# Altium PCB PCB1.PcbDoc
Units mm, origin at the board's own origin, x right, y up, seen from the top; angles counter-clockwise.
Board outline 108.7 x 104.5 mm, 2 copper layers (Top Layer, Bottom Layer); 73 components, 40 nets, 200 pads, 22 vias.
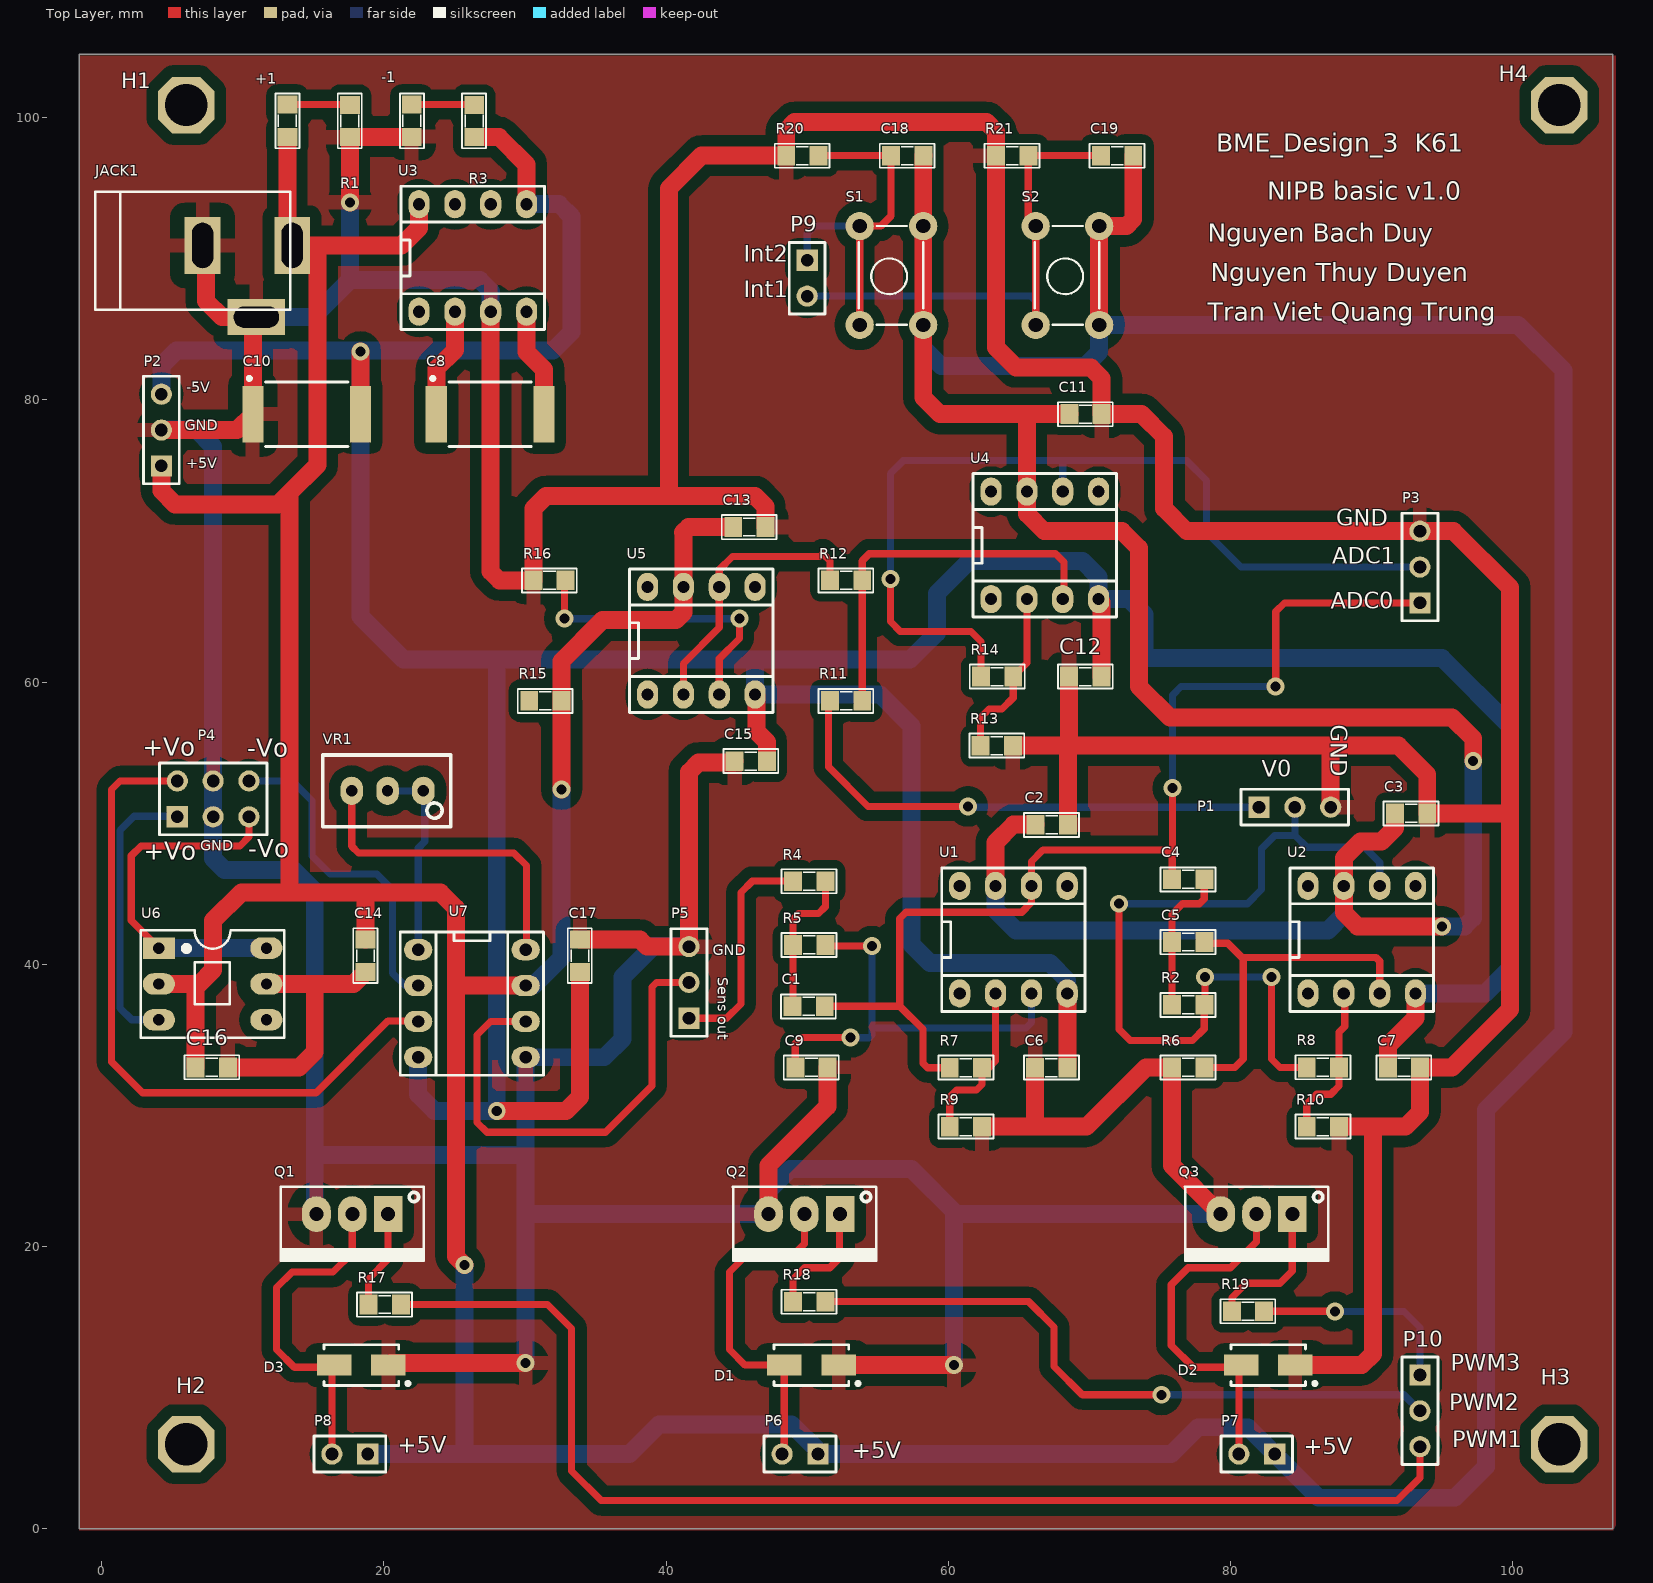
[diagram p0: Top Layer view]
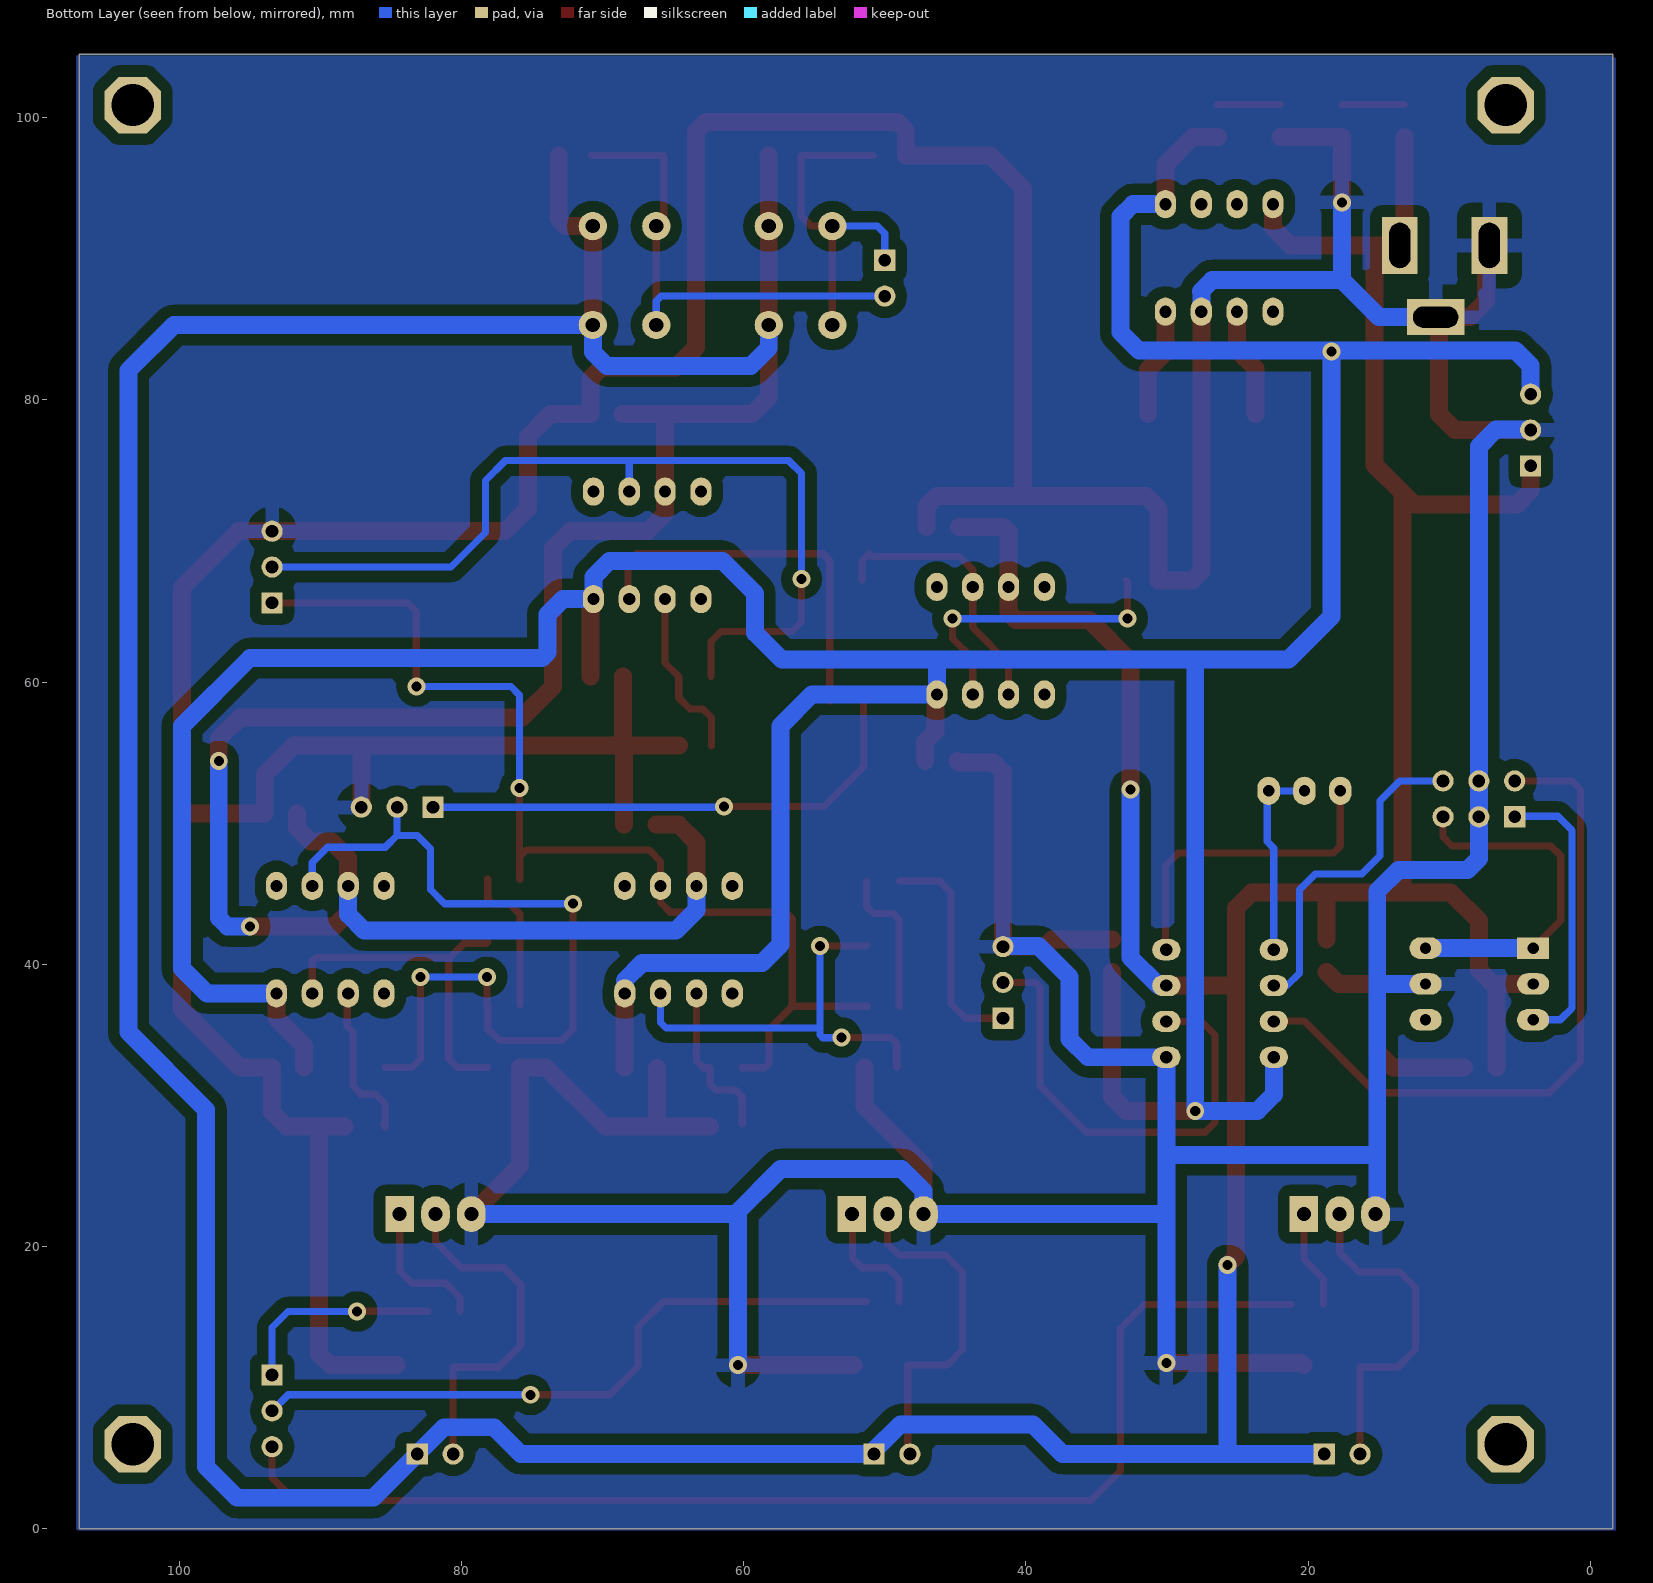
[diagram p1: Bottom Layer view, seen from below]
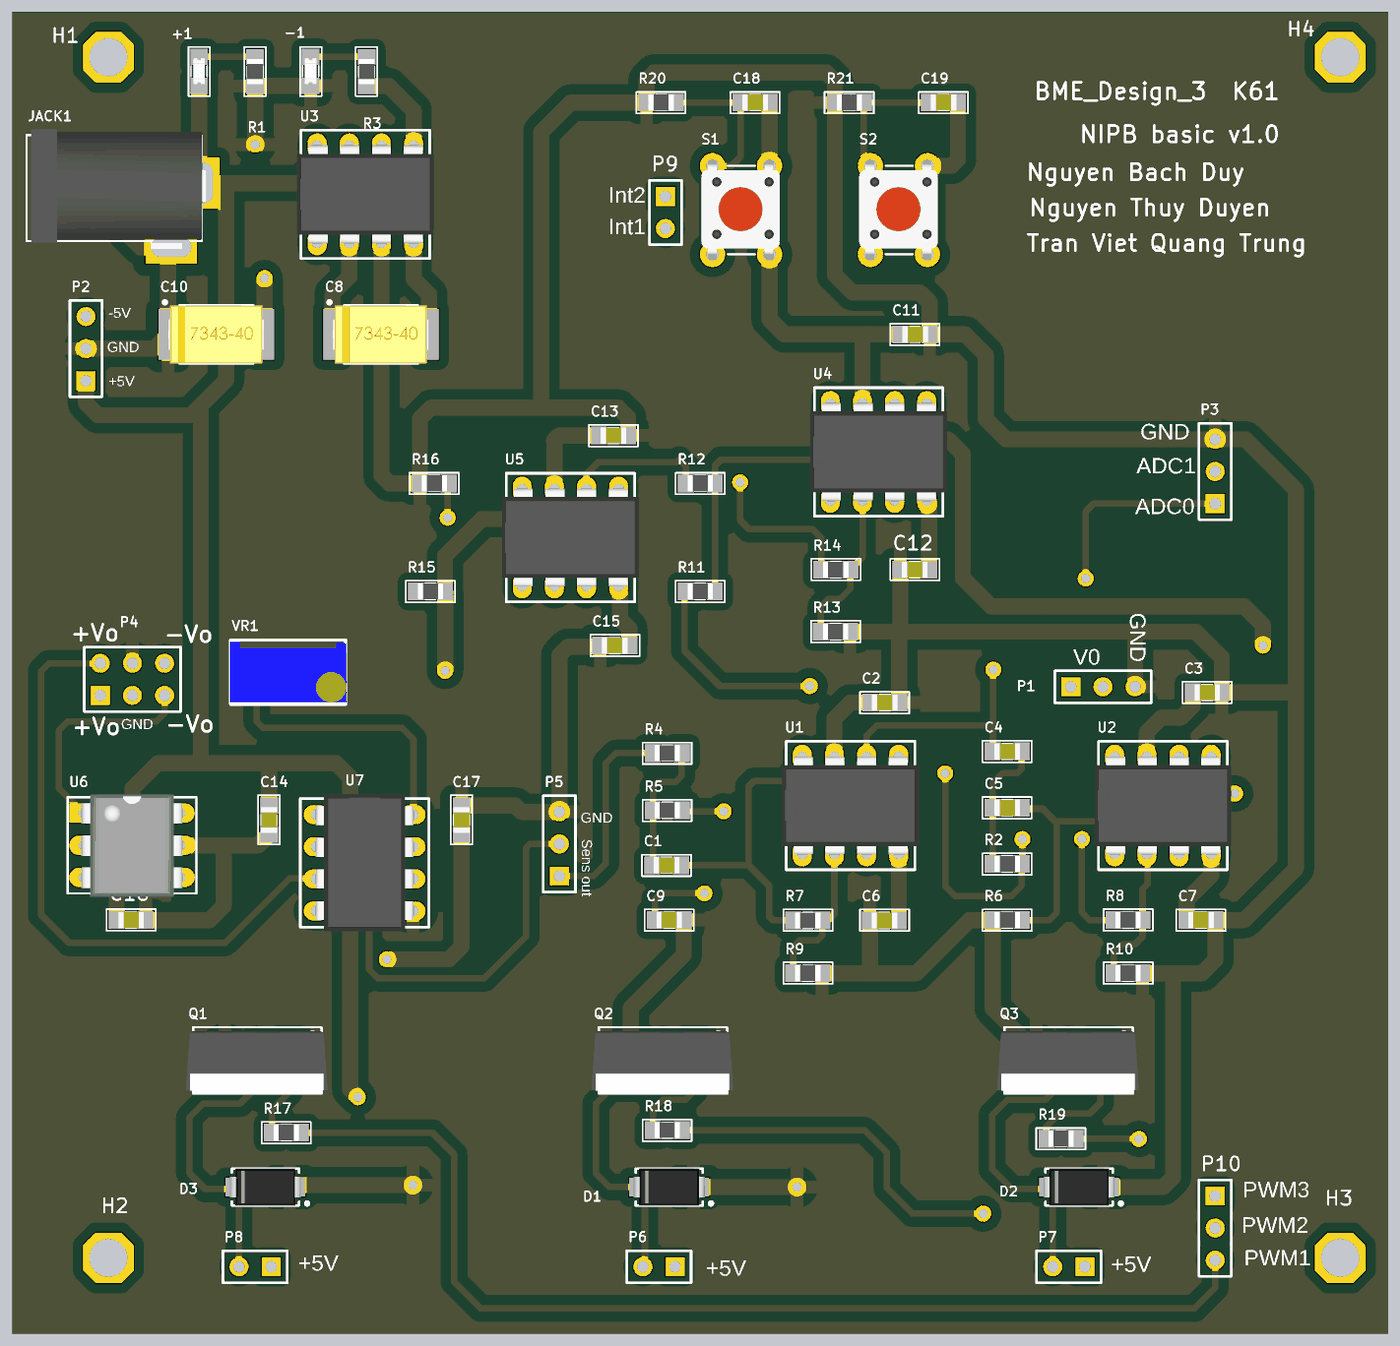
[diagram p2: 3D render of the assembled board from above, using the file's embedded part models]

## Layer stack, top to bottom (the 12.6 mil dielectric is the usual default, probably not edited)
Top Solder: solder mask 0.0102, Solder Resist, Dk 3.5
Top Layer: signal copper 0.0356
Dielectric 1: dielectric 0.32, FR-4, Dk 4.8
Bottom Layer: signal copper 0.0356
Bottom Solder: solder mask 0.0102, Solder Resist, Dk 3.5

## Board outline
-1.6,0 107.1,0 107.1,104.5 -1.6,104.5

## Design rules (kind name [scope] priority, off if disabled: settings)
Clearance Clearance_1 [All] p1: gap=0.4 ignorepadtopadclearanceinfootprint=FALSE except(0.8: Arc-Fill Arc-Poly Arc-Region Track-Fill Track-Poly Track-Region SMDPad-Fill SMDPad-Poly SMDPad-Region THPad-Fill THPad-Poly THPad-Region Via-Fill Via-Poly Via-Region Fill-Fill Fill-Poly Fill-Region Poly-Poly Poly-Region Region-Region)
Clearance polygon_clearance [InPolygon] p2: gap=2 ignorepadtopadclearanceinfootprint=FALSE
PolygonConnect [All] p1: connectstyle=Relief reliefconductorwidth=1 reliefentries=4 polygonreliefangle="90 Angle" airgapwidth=1
RoutingVias [All] p1: holewidth=1.016 width=0.635 viastyle="Through Hole" minholewidth=1.016 minwidth=0.635 maxholewidth=1.016 maxwidth=0.635
SolderMaskExpansion [All] p1: expansion=0.102
Width [All] p1: maxlimit=1.27 minlimit=0.3 preferedwidth=0.508
30 further rules are at their usual default settings.

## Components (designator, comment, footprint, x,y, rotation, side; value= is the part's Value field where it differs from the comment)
+1 "LED" "LED SMD 0805" 13.1,99.8 r90 top
-1 "LED" "LED SMD 0805" 21.906,99.8 r90 top
C1 "1uF" "0805 CAP" 50.1,37.039 r0 top
C2 "104" "0805 CAP" 67.325,49.9 r0 top
C3 "104" "0805 CAP" 92.8,50.7 r0 top
C4 "10uF" "0805 CAP" 77,46.035 r0 top
C5 "10uF" "0805 CAP" 77,41.59 r0 top
C6 "104" "0805 CAP" 67.3,32.675 r180 top
C7 "104" "0805 CAP" 92.3,32.7 r0 top
C8 "10uF" "CAP TANTALUM SMD7434" 27.4,78.989 r0 top
C9 "1uF" "0805 CAP" 50.3,32.7 r0 top
C10 "10uF" "CAP TANTALUM SMD7434" 14.4,78.989 r0 top
C11 "104" "0805 CAP" 69.725,79 r0 top
C12 "104" "0805 CAP" 69.7,60.4 r180 top
C13 "104" "0805 CAP" 45.904,71 r0 top
C14 "104" "0805 CAP" 18.7,40.61 r270 top
C15 "104" "0805 CAP" 46,54.4 r180 top
C16 "104" "0805 CAP" 7.8,32.7 r180 top
C17 "104" "0805 CAP" 33.9,40.61 r270 top
C18 "104" "0805 CAP" 57.093,97.315 r0 top
C19 "104" "0805 CAP" 71.964,97.315 r0 top
D1 "DIODE" "DIODE SMA" 50.3,11.6 r180 top
D2 "DIODE" "DIODE SMA" 82.674,11.6 r180 top
D3 "DIODE" "DIODE SMA" 18.4,11.6 r180 top
H1 "HOLE" HOLE 6,100.9 r0 top
H2 "HOLE" HOLE 6,6 r0 top
H3 "HOLE" HOLE 103.3,6 r0 top
H4 "HOLE" HOLE 103.3,100.9 r0 top
JACK1 "JACK DC" "JACK DC" 10.328,88.41 r0 top value="Jac DC"
P1 "Header 3H" HDR1X3 82.02,51.143 r0 top
P2 "Header 3H" HDR1X3 4.232,75.329 r90 top
P3 "Header 3H" HDR1X3 93.424,65.62 r90 top
P4 "Header 3X2" HDR2X3 5.36,50.46 r0 top
P5 "Header 3H" HDR1X3 41.623,36.179 r90 top
P6 "Valve" HDR1X2 50.76,5.3 r180 top
P7 "Valve" HDR1X2 83.134,5.3 r180 top
P8 "Pump" HDR1X2 18.86,5.3 r180 top
P9 "Header 2H" HDR1X2 50,89.9 r270 top
P10 "Header 3H" HDR1X3 93.424,10.9 r270 top
Q1 "TIP41C" QTO-220 20.3,22.3 r180 top
Q2 "TIP41C" QTO-220 52.34,22.3 r180 top
Q3 "TIP41C" QTO-220 84.38,22.3 r180 top
R1 "10k" "0805 RESISTOR" 17.594,100.908 r270 top value="R1/4W - 1K"
R2 "33k" "0805 RESISTOR" 75.857,37.145 r0 top value="R1/4W - 1K"
R3 "10k" "0805 RESISTOR" 26.4,100.908 r270 top value="R1/4W - 1K"
R4 "33k" "0805 RESISTOR" 49,45.9 r0 top value="R1/4W - 1K"
R5 "33k" "0805 RESISTOR" 49,41.378 r0 top value="R1/4W - 1K"
R6 "33K" "0805 RESISTOR" 75.857,32.7 r0 top value="R1/4W - 1K"
R7 "5.6k" "0805 RESISTOR" 62.386,32.675 r180 top value="R1/4W - 1K"
R8 "5.6k" "0805 RESISTOR" 87.686,32.7 r180 top value="R1/4W - 1K"
R9 "10k" "0805 RESISTOR" 62.386,28.5 r180 top value="R1/4W - 1K"
R10 "10k" "0805 RESISTOR" 87.686,28.5 r180 top value="R1/4W - 1K"
R11 "10k" "0805 RESISTOR" 51.614,58.684 r0 top value="R1/4W - 1K"
R12 "10k" "0805 RESISTOR" 51.614,67.218 r0 top value="R1/4W - 1K"
R13 "10k" "0805 RESISTOR" 64.575,55.5 r180 top value="R1/4W - 1K"
R14 "10k" "0805 RESISTOR" 64.6,60.4 r180 top value="R1/4W - 1K"
R15 "10k" "0805 RESISTOR" 30.3,58.684 r0 top value="R1/4W - 1K"
R16 "2.2k" "0805 RESISTOR" 30.6,67.218 r0 top value="R1/4W - 1K"
R17 "10k" "0805 RESISTOR" 18.914,15.9 r0 top value="R1/4W - 1K"
R18 "10k" "0805 RESISTOR" 49,16.1 r0 top value="R1/4W - 1K"
R19 "10k" "0805 RESISTOR" 80.1,15.425 r0 top value="R1/4W - 1K"
R20 "10k" "0805 RESISTOR" 48.515,97.315 r0 top value="R1/4W - 1K"
R21 "10k" "0805 RESISTOR" 63.386,97.315 r0 top value="R1/4W - 1K"
S1 "SWITCH" "SW 4PIN" 58.222,92.318 r270 top
S2 "SWITCH" "SW 4PIN" 70.694,92.318 r270 top
U1 "LM741" "DIP 8" 64.617,41.755 r0 top
U2 "LM741" "DIP 8" 89.3,41.755 r0 top
U3 "ICL7660" "DIP 8" 26.3,90.064 r0 top
U4 "LM741" "DIP 8" 66.838,69.7 r0 top
U5 "LM741" "DIP 8" 42.498,62.938 r0 top
U6 "MPS20N0040D" "DIP 6" 4.056,41.153 r270 top
U7 "INA-129" "DIP 8" 26.241,37.229 r270 top
VR1 "10K" RVAR 20.26,52.3 r180 top value="VR 10K"

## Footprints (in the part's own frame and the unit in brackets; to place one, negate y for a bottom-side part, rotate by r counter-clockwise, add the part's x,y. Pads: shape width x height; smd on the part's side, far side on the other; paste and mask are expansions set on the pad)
"0805 CAP" [mil] "Compoment SMD 80x50mil"
  rect 50x55 smd: 1(-45,0) 2(45,0)
  silkscreen extent -77,-34 76,33, body extent -40,-25 40,25, height 24
"0805 RESISTOR" [mil] "Compoment SMD 80x50mil"
  rect 50x55 smd: 1(0,0) 2(90,0)
  silkscreen extent -32,-34 121,33, body extent 6,-25 84,25, height 24
"CAP TANTALUM SMD7434" [mm] "227C-220uF 16V"
  rect 1.5x4 smd: 1(-3.683,0) 2(3.937,0)
  silkscreen extent -4.06,-2.29 3.05,2.66, body extent -3.68,-2.3 3.92,2.3, height 4
"DIODE SMA" [mm]
  rect 2.45x1.5 smd: 1(-1.925,0) 2(1.925,0)
  silkscreen extent -3.43,-1.45 2.65,1.45, body extent -2.8,-1.48 2.8,1.47, height 2.7
"DIP 6" [mil] "6 PIN, W 300mil, Pin to pin 100mil"
  rect 60x90 hole 31.5: 1(0,0)
  oval 60x90 hole 31.5: 2(100,0) 3(200,0) 4(200,300) 5(100,300) 6(0,300)
  silkscreen extent -50,-50 250,350, body extent -58,-7 260,307, height 170
"DIP 8" [mm] "W.300/L.400"
  oval 1.5x2 hole 0.864: 1(-3.81,-3.81) 2(-1.27,-3.81) 3(1.27,-3.81) 4(3.81,-3.81) 5(3.81,3.81) 6(1.27,3.81) 7(-1.27,3.81) 8(-3.81,3.81)
  silkscreen extent -5.08,-5.08 5.08,5.08, body extent -5.4,-3.88 5.4,3.88, height 4.5
HDR1X2 [mm] "Connector; Header; 2 Position"
  rect 1.5x1.5 hole 0.9: 1(0,0)
  round 1.5 hole 0.9: 2(2.54,0)
  silkscreen extent -1.27,-1.27 3.81,1.27
HDR1X3 [mm] "Connector; Header; 3 Position"
  rect 1.5x1.5 hole 0.9: 1(0,0)
  round 1.5 hole 0.9: 2(2.54,0) 3(5.08,0)
  silkscreen extent -1.27,-1.27 6.35,1.27
HDR2X3 [mm] "Connector; Header; 3x2 Position"
  rect 1.5x1.5 hole 0.9: 1(0,0)
  round 1.5 hole 0.9: 2(0,2.54) 3(2.54,0) 4(2.54,2.54) 5(5.08,0) 6(5.08,2.54)
  silkscreen extent -1.27,-1.27 6.35,3.81
HOLE [mm]
  oct 4x4 hole 3: H(0,0)
"JACK DC" [mm] "Jac DC input"
  rect 2.54x4.064 hole 1.5 slot 3.2 at 90 deg: 1(3.175,2.54) 2(-3.175,2.54)
  rect 4.064x2.54 hole 1.5 slot 3.2 at 0 deg: 3(0.635,-2.54)
  silkscreen extent -10.79,-2.03 3.05,6.35, body extent -10.42,-2.67 3.4,6.84, height 11.02
"LED SMD 0805" [mil] "Compoment SMD 80x50mil"
  rect 50x55 smd: 1(-45.39,-2.58) 2(44.61,-2.58)
  silkscreen extent -77,-37 76,30, body extent -41,-21 41,15, height 33
QTO-220 [mil] "TO-220 - 1-2-3"
  rect 80x100 hole 39: 1(0,0)
  oval 80x100 hole 39: 2(100,0) 3(200,0)
  silkscreen extent -100,-76 300,130, body extent -119,-64 322,121, height 755
RVAR [mm] "Bien tro vi chinh"
  oval 1.6x2 hole 0.8: 1(-2.54,0) 2(0,0) 3(2.54,0)
  silkscreen extent -4.47,-2.54 4.6,2.54, body extent -4.54,-2.4 4.66,2.4, height 12.02
"SW 4PIN" [mm] "SW button 4pin, 250 x250 mil"
  round 2 hole 1: 1(0,0) 1(7,0) 2(0,-4.5) 2(7,-4.5)
  silkscreen extent 0,-4.57 6.98,0, body extent -0.52,-5.39 7.38,0.81, height 7

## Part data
C1 C2 C3 C4 C5 C6 C7 C9 C11 C12 C13 C14 C15 C16 C17 C18 C19: library part "CAP CERAMIC"
C8 C10: library part CAPACITOR
P6 P7 P8: library part "Header 2H"
Q1 Q2 Q3: "NPN 2W, BCE"
R1 R2 R3 R4 R5 R6 R7 R8 R9 R10 R11 R12 R13 R14 R15 R16 R17 R18 R19 R20 R21: library part RESISTOR
U3: library part ICL7660SIBAZ, "ICL7660 Series 1.5 - 12 Vin 45 mA 10-35 kHz CMOS Voltage Converter - SOIC-8", Package="SOIC-8 Intersil"
VR1: library part "VAR RES"

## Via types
v1: diameter 1.27, hole 0.711, Top Layer to Bottom Layer, 22 vias

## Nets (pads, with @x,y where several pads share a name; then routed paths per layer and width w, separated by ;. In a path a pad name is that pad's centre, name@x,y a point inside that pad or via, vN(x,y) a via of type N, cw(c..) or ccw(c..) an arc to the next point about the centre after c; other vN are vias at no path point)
+5V: +1.1 C2.1 C3.1 C11.1 C13.1 C14.1 C16.2 C18.2 C19.2 JACK1.1 P2.1 P6.1 P7.1 P8.1 R15.2 S1.1 S2.1 U1.7 U2.7 U3.8 U4.7 U5.7 U6.2 U7.7 | length 576.6
  Top Layer w1.27: U6.2 6.913,38.613 ; P2.1 4.232,73.568 5.2,72.6 12.5,72.6 13.3,73.4 ; C16.2 6.657,38.357 6.913,38.613 ; +1.1 13.165,91.288 JACK1.1 15.3,90.95 ; C14.1 18.7,44.5 ; U3.8 22.49,92.19 21.25,90.95 15.3,90.95 ; v1(25.7,18.7) 25.1,19.3 25.1,44 24,45.1 13.3,45.1 ; U7.7 25.701,38.499 ; v1(32.6,52.4) 32.6,58.67 R15.2 32.586,61.486 35.5,64.4 40.7,64.4 41.228,64.928 U5.7 41.228,70.572 41.2,70.6 41.6,71 C13.1 ; C18.2 58.222,97.301 58.222,92.318 58.222,85.318 58.222,80.178 59.4,79 65.568,79 ; U1.7 63.347,48.647 64.6,49.9 C2.1 ; C11.1 65.568,79 ; S2.1@70.694,85.318 70.694,92.318 72.618,92.318 73.107,92.807 C19.2 ; C3.1 91.657,49.657 90.7,48.7 89.2,48.7 88.03,47.53 U2.7 88.03,43.67 89,42.7 v1(95,42.7) ; v1(97.2,54.4) 97.2,56 95.7,57.5 75.7,57.5 73.5,59.7 73.5,69.5 72.3,70.7 66.8,70.7 65.568,71.932 U4.7 65.568,79 ; 6.913,38.613 7.9,39.6 7.9,43.1 9.9,45.1 13.3,45.1 ; 13.3,45.1 13.3,73.4 ; 13.3,73.4 15.3,75.4 15.3,90.95 ; 25.7,38.5 25.701,38.499
  Bottom Layer w1.27: P8.1 25.8,5.3 ; v1(25.7,18.7) 25.7,5.4 25.8,5.3 ; U7.7 30.599,38.499 32.6,40.5 v1(32.6,52.4) ; S1.1@58.222,85.318 58.222,83.678 59.5,82.4 69.7,82.4 70.694,83.394 70.694,85.318 100.382,85.318 103.6,82.1 103.6,35.2 98.1,29.7 98.1,4.4 95.9,2.2 86.234,2.2 P7.1 81.234,7.2 77.7,7.2 75.8,5.3 P6.1 50.76,5.54 48.9,7.4 39.5,7.4 37.4,5.3 25.8,5.3 ; U1.7 63.347,43.853 64.8,42.4 86.9,42.4 88.03,43.53 U2.7 ; v1(95,42.7) 96.6,42.7 97.2,43.3 v1(97.2,54.4)
-5V: C6.1 C7.1 C10.2 C12.1 C15.1 C17.2 P2.3 R3.2 U1.4 U2.4 U3.5 U4.4 U5.4 U7.4 | length 314.2
  Top Layer w1.27: C10.2 v1(18.337,83.437) ; R3.2 28.178,98.622 30.11,96.69 U3.5 ; v1@28.3,29.6 32.9,29.6 33.9,30.6 C17.2 ; U5.4 46.4,59.036 46.4,56.5 47.143,55.757 C15.1 ; U1.4 68.443,37.929 C6.1 ; U4.4 70.843,65.695 C12.1 ; C7.1 91.157,34.257 93.11,36.21 U2.4
  Bottom Layer w1.27: P2.3 4.232,82.432 5.3,83.5 32,83.5 33.3,84.8 33.3,93 32.426,93.874 U3.5 ; v1(18.337,83.437) 18.337,64.663 21.4,61.6 28,61.6 ; U7.4 22.431,30.769 23.6,29.6 v1(28,29.6) 28,61.6 ; U1.4 68.427,38.873 67.2,40.1 58.7,40.1 57.4,41.4 57.4,56.9 55.172,59.128 U5.4 46.308,61.6 ; U2.4 98.045,37.945 99.8,39.7 99.8,56.9 95,61.7 74.3,61.7 73.9,62.1 73.9,64.8 72.81,65.89 U4.4 70.648,67.452 69.5,68.6 61.5,68.6 59.2,66.3 59.2,63.5 57.3,61.6 46.308,61.6 ; 28,61.6 46.308,61.6
ADC0: C1.2 C4.1 P3.1 R7.2 U1.6 | length 79.5
  Top Layer w0.508: C1.2 56.561,37.039 ; R7.2 58.525,32.675 58.2,33 58.2,35.4 56.561,37.039 ; v1(75.9,52.5) 75.9,46.078 C4.1 75.857,47.643 75.4,48.1 66.7,48.1 65.887,47.287 U1.6 65.887,44.387 65.2,43.7 57,43.7 56.561,43.261 56.561,37.039 ; v1(83.2,59.7) 83.2,65 83.82,65.62 P3.1
  Bottom Layer w0.508: v1(75.9,52.5) 75.9,59.1 76.5,59.7 v1(83.2,59.7)
ADC1: P3.2 R14.2 U4.6 | length 65.4
  Top Layer w0.508: v1(55.9,67.3) 55.9,64.3 56.6,63.6 61.6,63.6 62.314,62.886 R14.2
  Bottom Layer w0.508: v1(55.9,67.3) 55.9,74.8 56.8,75.7 68.1,75.7 ; U4.6 68.108,75.692 68.1,75.7 ; P3.2 80.74,68.16 78.3,70.6 78.3,74.3 76.9,75.7 68.1,75.7
GND: -1.1 C2.2 C3.2 C6.2 C7.2 C9.2 C10.1 C11.2 C12.2 C13.2 C14.2 C15.2 C16.1 C17.1 D1.1 D2.1 D3.1 JACK1.2 JACK1.3 P1.3 P2.2 P3.3 P4.3 P4.4 P5.3 Q1.3 Q2.3 Q3.3 R1.2 R6.1 R9.1 R10.1 R13.1 R16.1 R20.1 R21.1 U3.3 U6.5 U7.5 | length 625.1
  Top Layer w1.27: P2.2 9.597,77.869 C10.1 10.717,85.624 JACK1.3 8.53,85.87 7.4,87 7.4,90.703 JACK1.2 ; C16.1 14,32.7 15.1,33.8 15.1,38.613 ; U6.5 15.1,38.613 ; v1(17.6,94) 17.594,94.006 R1.2 17.619,98.647 -1.1 ; C14.2 17.846,38.613 15.1,38.613 ; D3.1 20.476,11.751 v1(30.051,11.751) ; U3.3 27.57,67.83 28.182,67.218 R16.1 30.6,72.3 31.5,73.2 40.1,73.2 ; C17.1 38.147,41.753 38.641,41.259 P5.3 41.623,53.623 42.3,54.3 44.757,54.3 C15.2 ; C13.2 47.047,72.453 46.3,73.2 40.1,73.2 ; Q2.3 47.26,25.76 51.443,29.943 C9.2 ; D1.1 v1@60.2,11.6 ; R9.1 66.093,28.5 ; R13.1 68.3,55.5 ; C6.2 66.157,28.564 66.093,28.5 ; C2.2 68.468,55.332 68.3,55.5 ; C12.2 68.557,55.757 68.3,55.5 ; Q3.3 75.857,25.743 R6.1 74,32.7 69.8,28.5 66.093,28.5 ; D2.1 89.3,11.6 90.1,12.4 90.1,28.5 ; P1.3 87.1,55.1 87.5,55.5 ; R10.1@88.286,28.5 90.1,28.5 ; 40.1,73.2 40.2,73.3 40.2,95 42.515,97.315 R20.1 48.515,99.115 49.1,99.7 62.7,99.7 63.386,99.014 R21.1 63.386,83.714 64.8,82.3 70.1,82.3 70.868,81.532 C11.2 73.7,79 75.3,77.4 75.3,72.3 76.9,70.7 P3.3 95.8,70.7 99.8,66.7 99.8,50.7 ; 68.3,55.5 87.5,55.5 ; 87.5,55.5 91.9,55.5 93.943,53.457 C3.2 99.8,50.7 ; 90.1,28.5 92.4,28.5 93.443,29.543 C7.2 95.7,32.7 99.8,36.8 99.8,50.7
  Bottom Layer w1.27: P2.2 4.263,77.9 6.7,77.9 7.9,76.7 P4.4 P4.3 7.9,47.5 8.7,46.7 13.6,46.7 15.1,45.2 15.1,38.6 ; JACK1.3 14.97,85.87 17.6,88.5 ; U6.5 15.087,38.613 15.1,38.6 ; Q1.3 15.1,22.42 15.1,26.5 ; v1(17.6,94) 17.6,88.5 ; U3.3 27.57,87.67 27.6,87.7 26.8,88.5 17.6,88.5 ; v1(30.051,11.751) 30.051,22.2 ; P5.3 41.582,41.3 39.1,41.3 36.9,39.1 36.9,34.7 35.619,33.419 U7.5 30.051,26.5 ; v1(60.4,11.6) 60.4,22.1 60.6,22.3 ; Q3.3 60.6,22.3 ; 15.1,26.5 30.051,26.5 ; 15.1,26.5 15.1,38.6 ; 30.051,22.2 30.051,26.5 ; 30.051,22.2 30.151,22.3 Q2.3 47.26,23.96 48.8,25.5 57.4,25.5 60.6,22.3
Interrupt2: C19.1 P9.2 R21.2 S2.2 | length 35.4
  Top Layer w0.508: S2.2@66.194,85.318 66.194,92.318 65.672,92.84 R21.2 C19.1
  Bottom Layer w0.508: P9.2 65.84,87.36 66.194,87.006 S2.2@66.194,85.318
Net+1_2: +1.2 R1.1 | length 4.4
  Top Layer w0.508: +1.2 17.568,100.933 R1.1
Net-1_2: -1.2 R3.1 | length 4.4
  Top Layer w0.508: -1.2 26.375,100.933 R3.1
NetC1_1: C1.1 R4.2 R5.1 | length 10.6
  Top Layer w0.508: C1.1 49,37.082 R5.1 49,43.2 49.4,43.6 50.8,43.6 51.286,44.086 R4.2
NetC4_2: C4.2 C5.1 R2.1 | length 10.5
  Top Layer w0.508: R2.1 C5.1 75.857,43.557 76.6,44.3 77.8,44.3 78.143,44.643 C4.2
NetC5_2: C5.2 R6.2 U2.3 | length 25.5
  Top Layer w0.508: R6.2 80.3,32.7 80.9,33.3 80.9,40.4 80.8,40.5 ; C5.2 78.233,41.5 79.8,41.5 80.8,40.5 ; U2.3 90.57,40.23 90.3,40.5 80.8,40.5
NetC8_1: C8.1 U3.2 | length 7.8
  Top Layer w1.27: C8.1 23.717,82.217 25.03,83.53 U3.2
NetC8_2: C8.2 U3.4 | length 7.8
  Top Layer w1.27: U3.4 30.11,83.39 31.337,82.163 C8.2
NetC9_1: C9.1 R5.2 U1.3 | length 30.6
  Top Layer w0.508: C9.1 49.157,34.374 49.6,34.817 53.067,34.817 53.083,34.8 v1@53.1,34.8 ; R5.2 51.364,41.3 v1(54.6,41.3)
  Bottom Layer w0.508: v1(53.083,34.817) 53.1,34.8 54.4,34.8 54.6,35 54.6,35.6 ; v1(54.6,41.3) 54.6,35.6 ; U1.3 65.887,35.887 65.5,35.5 54.7,35.5 54.6,35.6
NetC18_1: C18.1 P9.1 R20.2 S1.2 | length 24.8
  Top Layer w0.508: R20.2 C18.1 55.95,93.05 55.218,92.318 53.722,92.318 S1.2@53.722,85.318
  Bottom Layer w0.508: P9.1 50,91.8 50.518,92.318 S1.2@53.722,92.318
NetD1_2: D1.2 P6.2 Q2.2 | length 24.4
  Top Layer w0.508: P6.2 48.375,5.455 D1.2 45.6,11.6 44.5,12.7 44.5,18.2 45.7,19.4 49,19.4 49.8,20.2 Q2.2
NetD2_2: D2.2 P7.2 Q3.2 | length 25.1
  Top Layer w0.508: P7.2 80.594,11.445 77.355,11.445 75.8,13 75.8,17.3 77,18.5 80,18.5 81.84,20.34 Q3.2
NetD3_2: D3.2 P8.2 Q1.2 | length 24.1
  Top Layer w0.508: P8.2 16.32,11.445 13.655,11.445 12.4,12.7 12.4,17.1 13.5,18.2 16.4,18.2 17.76,19.56 Q1.2
NetP1_2: P1.2 R2.2 R8.2 U2.6 | length 59.2
  Top Layer w0.508: v1(72.1,44.3) 72.1,35.4 72.9,34.6 77.3,34.6 78.143,35.443 R2.2 78.2,37.202 v1(78.2,39.1) ; v1(82.9,39.1) 82.9,33.3 83.5,32.7 R8.2
  Bottom Layer w0.508: v1(72.1,44.3) 81.2,44.3 82.2,45.3 82.2,48.2 83.14,49.14 84.56,49.14 ; v1(78.2,39.1) v1(82.9,39.1) ; P1.2 84.56,49.14 ; U2.6 90.57,47.23 89.5,48.3 85.4,48.3 84.56,49.14
NetP4_1: P4.1 U6.3 | length 20.2
  Bottom Layer w0.508: U6.3 2.127,36.073 1.3,36.9 1.3,49.5 2.3,50.5 5.32,50.5 P4.1
NetP4_2: P4.2 U7.3 | length 49
  Top Layer w0.508: P4.2 1.3,53 0.7,52.4 0.7,33.1 2.9,30.9 15.2,30.9 20.3,36 22.39,36 U7.3
NetP4_5: P4.5 U6.1 U6.6 | length 25.3
  Top Layer w0.508: U6.1 2.1,43.109 2.1,47.7 2.8,48.4 9.8,48.4 10.44,49.04 P4.5
  Bottom Layer w1.27: U6.1 U6.6
NetP4_6: P4.6 U7.2 | length 23.7
  Bottom Layer w0.508: P4.6 13.5,53 14.9,51.6 14.9,47.7 16.2,46.4 19.5,46.4 20.6,45.3 20.6,39.4 21.501,38.499 U7.2
NetP5_2: P5.2 U7.6 | length 33.9
  Top Layer w0.508: U7.6 27.559,35.959 26.6,35 26.6,28.8 27.3,28.1 35.7,28.1 39,31.4 39,38.4 39.319,38.719 P5.2
NetQ1_1: Q1.1 R17.1 | length 7
  Top Layer w0.508: R17.1 18.914,17.714 20.3,19.1 Q1.1
NetQ2_1: Q2.1 R18.1 | length 8.6
  Top Layer w0.508: R18.1 49,17.7 49.8,18.5 51.6,18.5 52.3,19.2 52.3,22.26 Q2.1
NetQ3_1: Q3.1 R19.1 | length 10.1
  Top Layer w0.508: R19.1 80.1,16.4 81.1,17.4 83.5,17.4 84.38,18.28 Q3.1
NetR7_1: R7.1 R9.2 U1.2 | length 11.7
  Top Layer w0.508: R9.2@60.1,28.7 60.1,30.6 60.6,31.1 62,31.1 62.386,31.486 R7.1 62.869,32.675 63.347,33.153 U1.2
NetR8_1: R8.1 R10.2 U2.2 | length 11.3
  Top Layer w0.508: R10.2@85.514,28.614 R10.2 85.4,30.1 86.1,30.8 87.1,30.8 87.686,31.386 R8.1 87.686,35.186 88.1,35.6 88.1,37.875 U2.2
NetR11_2: R11.2 R12.2 U4.3 | length 27.3
  Top Layer w0.508: R11.2 R12.2 53.9,68.6 54.4,69.1 67.6,69.1 68.2,68.5 68.2,65.982 U4.3
NetR13_2: R13.2 R14.1 U4.2 | length 12.3
  Top Layer w0.508: R13.2 62.289,57.489 62.9,58.1 63.8,58.1 64.6,58.9 R14.1 65.568,61.368 U4.2
NetR16_2: R16.2 U5.3 | length 21.1
  Top Layer w0.508: v1(32.8,64.5) 32.8,67.132 R16.2 ; U5.3 43.768,61.668 45.2,63.1 v1(45.2,64.5)
  Bottom Layer w0.508: v1(32.8,64.5) v1(45.2,64.5)
NetU7_1: U7.1 VR1.1 VR1.2 | length 14
  Bottom Layer w0.508: VR1.2 VR1.1 22.9,52.2 22.9,48.7 22.431,48.231 U7.1
NetU7_8: U7.8 VR1.3 | length 22.9
  Top Layer w0.508: VR1.3 17.72,48.38 18.2,47.9 29.2,47.9 30.1,47 30.1,41.088 U7.8
PWM1: P10.3 R17.2 | length 86.8
  Top Layer w0.508: R17.2 31.6,15.9 33.3,14.2 33.3,4.1 35.4,2 91.8,2 93.424,3.624 P10.3
PWM2: P10.2 R18.2 | length 47
  Top Layer w0.508: R18.2 65.7,16.1 67.5,14.3 67.5,11.5 69.5,9.5 v1(75.1,9.5)
  Bottom Layer w0.508: v1(75.1,9.5) 92.284,9.5 P10.2
PWM3: P10.1 R19.2 | length 14.9
  Top Layer w0.508: R19.2 87.375,15.425 v1(87.4,15.4)
  Bottom Layer w0.508: v1(87.4,15.4) 92.3,15.4 93.424,14.276 P10.1
Sensor_Pressure_Out: P5.1 R4.1 | length 16
  Top Layer w0.508: P5.1 44.279,36.179 45.3,37.2 45.3,45.1 46.1,45.9 R4.1
V0: P1.1 R11.1 | length 36.4
  Top Layer w0.508: R11.1 51.5,58.57 51.5,54 54.3,51.2 v1(61.4,51.2)
  Bottom Layer w0.508: v1(61.4,51.2) 61.457,51.143 P1.1
V1: R12.1 U5.2 U5.6 | length 19.8
  Top Layer w0.508: U5.2 41.228,61.328 43.768,63.868 U5.6 43.768,67.968 44.7,68.9 50.9,68.9 51.1,69.1 51.614,68.586 R12.1
pads on no net: H1.H H2.H H3.H H4.H R15.1 U1.1 U1.5 U1.8 U2.1 U2.5 U2.8 U3.1 U3.6 U3.7 U4.1 U4.5 U4.8 U5.1 U5.5 U5.8 U6.4

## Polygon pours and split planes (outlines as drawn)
GND on Bottom Layer "Bottom-Layer" (solid, remove dead copper, pour order 32): -1.7,104.7 -1.4,104.4 107.3,104.4 107.3,0 107.2,-0.1 -1.8,-0.1 -1.8,104.6
GND on Top Layer "Top Layer-No Net" (solid, remove dead copper, pour order 30): -1.7,104.7 -1.6,104.6 -1.6,-0.1 107.3,-0.1 107.5,0.1 107.3,0.3 107.3,104.4 -1.7,104.4 -1.8,104.3

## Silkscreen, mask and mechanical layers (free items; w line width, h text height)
Top Overlay:
  text "BME_Design_3  K61" at 79,97.6 h1.3
  text "NIPB basic v1.0" at 82.6,94.2 h1.3
  text "Nguyen Bach Duy" at 78.4,91.2 h1.3
  text "Int2" at 45.5,89.4 h2
  text "Nguyen Thuy Duyen" at 78.6,88.4 h1.3
  text "Int1" at 45.5,86.9 h2
  text "Tran Viet Quang Trung" at 78.4,85.6 h1.3
  text "-5V" at 6,80.3 h1.3
  text "GND" at 5.9,77.6 h1.3
  text "+5V" at 6,74.9 h1.3
  text "GND" at 87.5,70.7 h2
  text "ADC1" at 87.2,68 h2
  text "ADC0" at 87.1,64.8 h2
  text "GND" at 86.7,57 h2 r270
  text "V0" at 82.2,52.9 h2
  text "GND" at 7,47.8 h1.3
  text "GND" at 43.3,40.4 h1.3
  text "Sens out" at 43.4,39.1 h1.3 r270
  text "PWM3" at 95.6,10.8 h2
  text "PWM2" at 95.5,8 h2
  text "PWM1" at 95.7,5.4 h2
  text "+5V" at 21,5 h2
  text "+5V" at 85.2,4.9 h2
  text "+5V" at 53.2,4.6 h2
